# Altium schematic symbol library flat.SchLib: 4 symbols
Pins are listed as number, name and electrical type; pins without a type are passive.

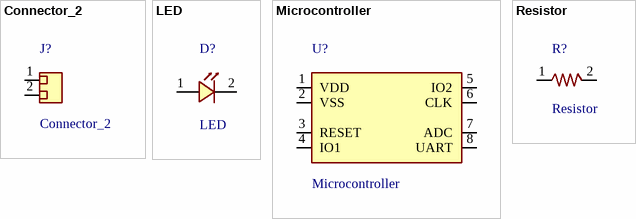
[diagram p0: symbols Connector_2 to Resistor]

## Connector_2
designator J?
Generic two-circuit connector
pins: 1 Passive, 2 Passive

## LED
designator D?
Generic light-emitting diode
pins: 1 A, 2 K

## Microcontroller
designator U?
Conceptual controller block; not a device pinout
pins: 1 VDD, 2 VSS, 3 RESET, 4 IO1, 5 IO2, 6 CLK, 7 ADC, 8 UART

## Resistor
designator R?
Generic two-terminal resistor
pins: 1 A, 2 B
